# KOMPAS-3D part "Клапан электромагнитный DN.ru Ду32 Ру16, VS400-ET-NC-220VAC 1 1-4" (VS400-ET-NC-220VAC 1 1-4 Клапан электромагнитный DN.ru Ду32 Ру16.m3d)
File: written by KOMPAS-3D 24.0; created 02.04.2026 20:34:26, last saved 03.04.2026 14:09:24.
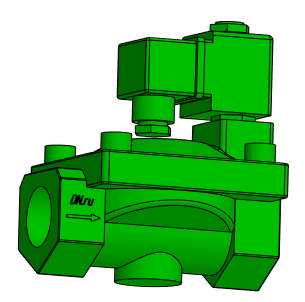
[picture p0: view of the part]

Document properties: Автор: artio; Полное имя файла: C:\Users\artio\OneDrive\Рабочий стол\Клапан электромагнитный DN.ru\VS400-ET-NC-220VAC 1 1-4 Клапан электромагнитный DN.ru Ду32 Ру16.m3d

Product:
- Body: Тело 1  | qty 1
    Масса: 4.144257
- Part/product: Клапан электромагнитный DN.ru Ду32 Ру16  | designation VS400-ET-NC-220VAC 1 1-4
    Масса: 2.569
    Раздел спецификации: Прочие изделия
    Примечание: D130-04694
    additional columns: ef56311e-7521-43dc-8291-0e6108b3d81d; VS400-ET-NC-220VAC 1 1-4; artio; c; Шероховатость не задана; Да

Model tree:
1. Операция без истории:1

Expressions: VS400-ET-NC-220VAC 1 1-4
